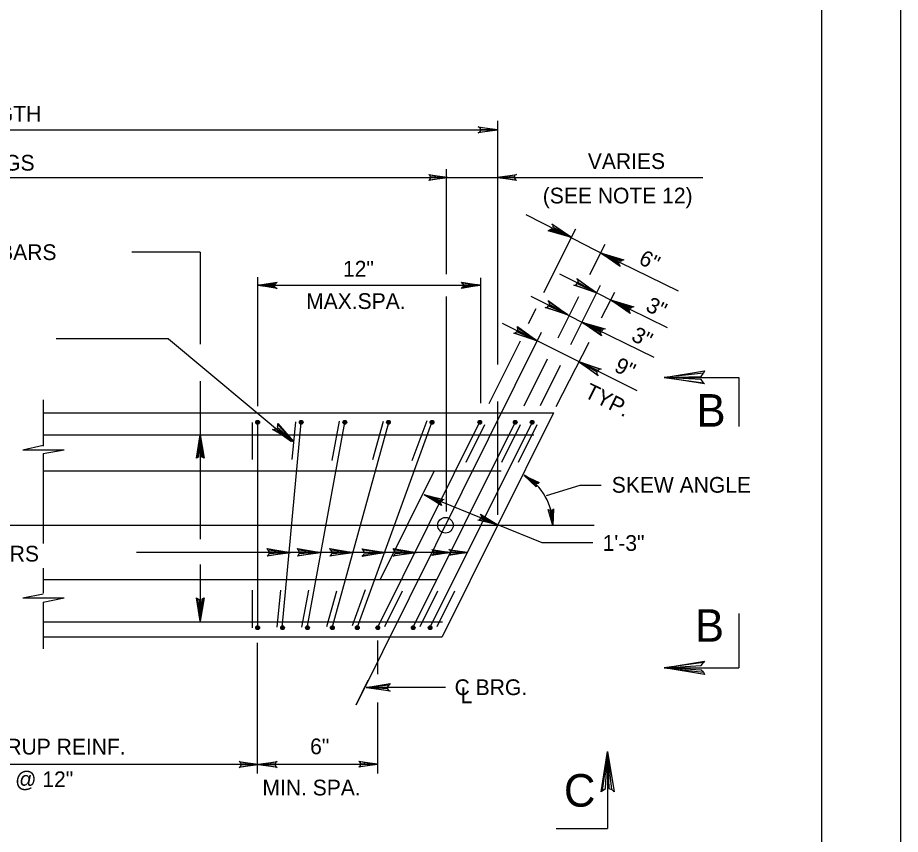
# Model space of a CAD drawing. Extents: x 642009 to 642864, y 298232 to 300014.
# Drawn here: x 642681.6 to 642849.7, y 299702.6 to 299858.2 of the extents above; entities that cross this region are included whole.
import ezdxf

# ---------------------------------------------------------------- set-up
doc = ezdxf.new("R2010")
doc.units = 0
doc.layers.add('2', color=7, linetype='Continuous')
doc.layers.add('PLT-BNDY', color=7, linetype='Continuous')

msp = doc.modelspace()

# ---------------------------------------------------------------- linework, layer by layer
at = {"layer": '2'}
for p, q in [((642834.66, 299998.82), (642834.66, 299434.82)), ((642772.99, 299792.13), (642772.99, 299838.52)), ((642571.23, 299836.82), (642772.99, 299836.82)), ((642763.15, 299829.34), (642763.15, 299809.33)), ((642579.29, 299827.76), (642763.44, 299827.76)), ((642763.44, 299827.76), (642770.63, 299827.76)), ((642770.63, 299827.76), (642812.02, 299827.76)), ((642787.48, 299816.03), (642778.43, 299820.62)), ((642787.77, 299817.89), (642781.72, 299805.75)), ((642793.52, 299812.86), (642787.48, 299816.03)), ((642793.35, 299814.98), (642790.46, 299809.21)), ((642716.34, 299813.53), (642703.33, 299813.53)), ((642716.34, 299813.53), (642716.34, 299795.98)), ((642807.4, 299806.08), (642793.52, 299812.86)), ((642727.21, 299808.79), (642727.21, 299784.21)), ((642769.69, 299808.64), (642769.69, 299784.78)), ((642790.3, 299806.58), (642784.84, 299809.31)), ((642727.21, 299807.21), (642769.69, 299807.21)), ((642792.5, 299807.18), (642786.83, 299795.84)), ((642790.3, 299806.58), (642794.47, 299804.43)), ((642795.19, 299805.86), (642792.7, 299800.97)), ((642763.15, 299805.05), (642763.15, 299764.09)), ((642784.84, 299802.36), (642779.38, 299805.09)), ((642788.37, 299805.04), (642784.41, 299797.12)), ((642805.32, 299799.1), (642794.47, 299804.43)), ((642780.22, 299802.74), (642778.79, 299799.86)), ((642784.84, 299802.36), (642789.01, 299800.2)), ((642802.76, 299793.45), (642789.01, 299800.2)), ((642780.59, 299796.57), (642773.89, 299799.92)), ((642710.28, 299797), (642688.89, 299797)), ((642710.28, 299797), (642733.68, 299777.45)), ((642781.28, 299798.24), (642746.04, 299727.28)), ((642777.26, 299796.59), (642771.28, 299784.6)), ((642788.36, 299792.69), (642780.59, 299796.57)), ((642790.33, 299796.32), (642784.07, 299784.04)), ((642782.42, 299793.14), (642777.96, 299784.21)), ((642784.87, 299791.92), (642781.04, 299784.26)), ((642799.54, 299787.1), (642788.36, 299792.69)), ((642716.34, 299788.93), (642716.34, 299758.86)), ((642804.69, 299789.65), (642818.93, 299789.65)), ((642818.93, 299789.65), (642818.93, 299780.31)), ((642686.39, 299785.36), (642686.39, 299776.59)), ((642772.99, 299763.5), (642772.99, 299785.07)), ((642686.39, 299782.91), (642783.63, 299782.91)), ((642783.63, 299782.91), (642762.43, 299740.22)), ((642726.21, 299781.04), (642726.21, 299774)), ((642727.21, 299781.04), (642727.21, 299741.94)), ((642727.21, 299781.04), (642727.21, 299781.04)), ((642727.21, 299781.04), (642727.21, 299781.04)), ((642727.21, 299781.04), (642727.21, 299781.04)), ((642727.21, 299781.04), (642727.21, 299781.04)), ((642727.21, 299781.04), (642727.21, 299781.04)), ((642727.21, 299781.04), (642727.21, 299781.04)), ((642727.21, 299781.04), (642727.21, 299781.04)), ((642727.21, 299781.04), (642727.21, 299781.04)), ((642731.96, 299741.94), (642735.55, 299781.04)), ((642733.83, 299774), (642734.54, 299781.19)), ((642735.55, 299781.04), (642735.55, 299781.04)), ((642735.55, 299781.04), (642735.55, 299781.04)), ((642735.55, 299781.04), (642735.55, 299781.04)), ((642735.55, 299781.04), (642735.55, 299781.04)), ((642735.55, 299781.04), (642735.55, 299781.04)), ((642735.55, 299781.04), (642735.55, 299781.04)), ((642735.55, 299781.04), (642735.55, 299781.04)), ((642735.55, 299781.04), (642735.55, 299781.04)), ((642735.55, 299781.04), (642735.55, 299781.04)), ((642736.7, 299741.94), (642743.89, 299781.04)), ((642741.44, 299773.86), (642742.88, 299781.33)), ((642741.44, 299741.94), (642752.23, 299781.04)), ((642743.89, 299781.04), (642743.89, 299781.04)), ((642743.89, 299781.04), (642743.89, 299781.04)), ((642743.89, 299781.04), (642743.89, 299781.04)), ((642743.89, 299781.04), (642743.89, 299781.04)), ((642743.89, 299781.04), (642743.89, 299781.04)), ((642743.89, 299781.04), (642743.89, 299781.04)), ((642743.89, 299781.04), (642743.89, 299781.04)), ((642743.89, 299781.04), (642743.89, 299781.04)), ((642743.89, 299781.04), (642743.89, 299781.04)), ((642743.89, 299781.04), (642743.89, 299781.04)), ((642746.19, 299741.94), (642760.42, 299781.04)), ((642749.21, 299774), (642751.22, 299781.33)), ((642750.08, 299741.95), (642769.54, 299781.05)), ((642752.23, 299781.04), (642752.23, 299781.04)), ((642752.23, 299781.04), (642752.23, 299781.04)), ((642752.23, 299781.04), (642752.23, 299781.04)), ((642752.23, 299781.04), (642752.23, 299781.04)), ((642752.23, 299781.04), (642752.23, 299781.04)), ((642752.23, 299781.04), (642752.23, 299781.04)), ((642752.23, 299781.04), (642752.23, 299781.04)), ((642752.23, 299781.04), (642752.23, 299781.04)), ((642752.23, 299781.04), (642752.23, 299781.04)), ((642752.23, 299781.04), (642752.23, 299781.04)), ((642752.23, 299781.04), (642752.23, 299781.04)), ((642756.68, 299773.86), (642759.56, 299781.48)), ((642756.84, 299741.95), (642776.31, 299781.05)), ((642760.05, 299741.95), (642779.52, 299781.05)), ((642760.42, 299781.04), (642760.42, 299781.04)), ((642760.42, 299781.04), (642760.42, 299781.04)), ((642760.42, 299781.04), (642760.42, 299781.04)), ((642760.42, 299781.04), (642760.42, 299781.04)), ((642760.42, 299781.04), (642760.42, 299781.04)), ((642760.42, 299781.04), (642760.42, 299781.04)), ((642760.42, 299781.04), (642760.42, 299781.04)), ((642760.42, 299781.04), (642760.42, 299781.04)), ((642760.42, 299781.04), (642760.42, 299781.04)), ((642760.42, 299781.04), (642760.42, 299781.04)), ((642760.42, 299781.04), (642760.42, 299781.04)), ((642760.42, 299781.04), (642760.42, 299781.04)), ((642766.99, 299773.49), (642770.53, 299780.71)), ((642769.54, 299781.05), (642769.54, 299781.05)), ((642769.54, 299781.05), (642769.54, 299781.05)), ((642769.54, 299781.05), (642769.54, 299781.05)), ((642769.54, 299781.05), (642769.54, 299781.05)), ((642769.54, 299781.05), (642769.54, 299781.05)), ((642769.54, 299781.05), (642769.54, 299781.05)), ((642769.54, 299781.05), (642769.54, 299781.05)), ((642769.54, 299781.05), (642769.54, 299781.05)), ((642769.54, 299781.05), (642769.54, 299781.05)), ((642769.54, 299781.05), (642769.54, 299781.05)), ((642769.54, 299781.05), (642769.54, 299781.05)), ((642769.54, 299781.05), (642769.54, 299781.05)), ((642769.54, 299781.05), (642769.54, 299781.05)), ((642773.75, 299773.49), (642777.3, 299780.71)), ((642776.31, 299781.05), (642776.31, 299781.05)), ((642776.31, 299781.05), (642776.31, 299781.05)), ((642776.31, 299781.05), (642776.31, 299781.05)), ((642776.31, 299781.05), (642776.31, 299781.05)), ((642776.31, 299781.05), (642776.31, 299781.05)), ((642776.31, 299781.05), (642776.31, 299781.05)), ((642776.31, 299781.05), (642776.31, 299781.05)), ((642776.31, 299781.05), (642776.31, 299781.05)), ((642776.31, 299781.05), (642776.31, 299781.05)), ((642776.31, 299781.05), (642776.31, 299781.05)), ((642776.31, 299781.05), (642776.31, 299781.05)), ((642776.31, 299781.05), (642776.31, 299781.05)), ((642776.31, 299781.05), (642776.31, 299781.05)), ((642776.96, 299773.49), (642780.51, 299780.71)), ((642779.52, 299781.05), (642779.52, 299781.05)), ((642779.52, 299781.05), (642779.52, 299781.05)), ((642779.52, 299781.05), (642779.52, 299781.05)), ((642779.52, 299781.05), (642779.52, 299781.05)), ((642779.52, 299781.05), (642779.52, 299781.05)), ((642779.52, 299781.05), (642779.52, 299781.05)), ((642779.52, 299781.05), (642779.52, 299781.05)), ((642779.52, 299781.05), (642779.52, 299781.05)), ((642779.52, 299781.05), (642779.52, 299781.05)), ((642779.52, 299781.05), (642779.52, 299781.05)), ((642779.52, 299781.05), (642779.52, 299781.05)), ((642779.52, 299781.05), (642779.52, 299781.05)), ((642779.52, 299781.05), (642779.52, 299781.05)), ((642686.39, 299778.74), (642779.87, 299778.74)), ((642682.51, 299775.87), (642686.39, 299776.73)), ((642682.51, 299775.87), (642690.41, 299775.87)), ((642686.39, 299775.15), (642690.41, 299775.87)), ((642686.39, 299775.15), (642686.39, 299758.33)), ((642686.39, 299775.15), (642686.39, 299758.04)), ((642686.39, 299771.84), (642773.64, 299771.84)), ((642760.85, 299771.84), (642750.57, 299751.14)), ((642788.65, 299769.08), (642782.18, 299767.07)), ((642792.67, 299769.08), (642788.65, 299769.08)), ((642773.02, 299761.55), (642758.96, 299767.31)), ((642781.42, 299758.12), (642773.02, 299761.55)), ((642671.29, 299761.49), (642791.33, 299761.49)), ((642763.15, 299761.49), (642763.15, 299761.49)), ((642767.6, 299761.49), (642767.6, 299761.49)), ((642791.09, 299758.12), (642781.42, 299758.12)), ((642767.21, 299756.32), (642704.16, 299756.32)), ((642686.39, 299753.3), (642686.39, 299748.56)), ((642716.34, 299753.99), (642716.34, 299743.24)), ((642686.39, 299753.01), (642686.39, 299748.56)), ((642686.39, 299751.14), (642761.42, 299751.14)), ((642682.51, 299747.69), (642686.39, 299748.41)), ((642726.21, 299749.13), (642726.21, 299741.94)), ((642730.95, 299742.09), (642731.67, 299749.13)), ((642735.69, 299742.09), (642736.99, 299749.13)), ((642740.44, 299742.23), (642742.31, 299748.99)), ((642745.33, 299742.38), (642747.77, 299749.28)), ((642751.46, 299742.2), (642754.84, 299749)), ((642758.22, 299742.2), (642761.6, 299749)), ((642761.43, 299742.2), (642764.81, 299749)), ((642682.51, 299747.69), (642690.41, 299747.69)), ((642686.39, 299746.83), (642690.41, 299747.69)), ((642686.39, 299746.83), (642686.39, 299737.92)), ((642686.39, 299743.09), (642762.46, 299743.09)), ((642818.93, 299744.68), (642818.93, 299734.33)), ((642727.21, 299741.94), (642727.21, 299741.94)), ((642727.21, 299741.94), (642727.21, 299741.94)), ((642727.21, 299741.94), (642727.21, 299741.94)), ((642727.21, 299741.94), (642727.21, 299741.94)), ((642727.21, 299741.94), (642727.21, 299741.94)), ((642727.21, 299741.94), (642727.21, 299741.94)), ((642727.21, 299741.94), (642727.21, 299741.94)), ((642731.96, 299741.94), (642731.96, 299741.94)), ((642731.96, 299741.94), (642731.96, 299741.94)), ((642731.96, 299741.94), (642731.96, 299741.94)), ((642731.96, 299741.94), (642731.96, 299741.94)), ((642731.96, 299741.94), (642731.96, 299741.94)), ((642731.96, 299741.94), (642731.96, 299741.94)), ((642736.7, 299741.94), (642736.7, 299741.94)), ((642736.7, 299741.94), (642736.7, 299741.94)), ((642736.7, 299741.94), (642736.7, 299741.94)), ((642736.7, 299741.94), (642736.7, 299741.94)), ((642736.7, 299741.94), (642736.7, 299741.94)), ((642741.44, 299741.94), (642741.44, 299741.94)), ((642741.44, 299741.94), (642741.44, 299741.94)), ((642741.44, 299741.94), (642741.44, 299741.94)), ((642741.44, 299741.94), (642741.44, 299741.94)), ((642746.19, 299741.94), (642746.19, 299741.94)), ((642746.19, 299741.94), (642746.19, 299741.94)), ((642746.19, 299741.94), (642746.19, 299741.94)), ((642750.08, 299741.95), (642750.08, 299741.95)), ((642750.08, 299741.95), (642750.08, 299741.95)), ((642756.84, 299741.95), (642756.84, 299741.95)), ((642756.84, 299741.95), (642756.84, 299741.95)), ((642760.05, 299741.95), (642760.05, 299741.95)), ((642760.05, 299741.95), (642760.05, 299741.95)), ((642686.39, 299740.22), (642762.43, 299740.22)), ((642727.21, 299714.2), (642727.21, 299739.07)), ((642750.13, 299733.15), (642750.13, 299739.52)), ((642804.69, 299734.33), (642818.93, 299734.33)), ((642746.04, 299727.28), (642748.33, 299731.95)), ((642763.01, 299730.59), (642747.91, 299730.59)), ((642750.13, 299714.18), (642750.13, 299727.71)), ((642793.91, 299718.37), (642793.91, 299703.71)), ((642727.36, 299715.93), (642658.07, 299715.93)), ((642750.13, 299715.93), (642727.36, 299715.93)), ((642784.14, 299703.71), (642793.91, 299703.71))]:
    msp.add_line(p, q, dxfattribs=at)
for points in [[(642769.54, 299837.25), (642769.69, 299836.96), (642772.99, 299836.82), (642769.54, 299837.25), (642769.26, 299837.39), (642772.99, 299836.82), (642769.69, 299836.68), (642769.54, 299836.39), (642772.99, 299836.82), (642769.26, 299836.24), (642769.54, 299836.39)], [(642759.99, 299828.19), (642760.13, 299827.91), (642763.44, 299827.76), (642759.99, 299828.19), (642759.84, 299828.34), (642763.44, 299827.76), (642760.13, 299827.62), (642759.99, 299827.33), (642763.44, 299827.76), (642759.84, 299827.19), (642759.99, 299827.33)], [(642776.42, 299827.33), (642776.27, 299827.62), (642772.97, 299827.76), (642776.42, 299827.33), (642776.56, 299827.19), (642772.97, 299827.76), (642776.27, 299827.91), (642776.27, 299828.19), (642772.97, 299827.76), (642776.56, 299828.34), (642776.27, 299828.19)], [(642783.46, 299818.76), (642783.46, 299818.33), (642787.05, 299816.31), (642783.46, 299818.76), (642783.31, 299818.9), (642787.05, 299816.31), (642783.17, 299817.89), (642782.88, 299817.75), (642787.05, 299816.31), (642782.59, 299817.61), (642782.88, 299817.75)], [(642796.13, 299811.08), (642796.13, 299811.36), (642792.54, 299813.38), (642796.13, 299811.08), (642796.28, 299810.79), (642792.54, 299813.38), (642796.42, 299811.79), (642796.71, 299811.94), (642792.54, 299813.38), (642797, 299812.08), (642796.71, 299811.94)], [(642730.66, 299806.78), (642730.52, 299806.92), (642727.21, 299807.21), (642730.66, 299806.78), (642730.95, 299806.63), (642727.21, 299807.21), (642730.52, 299807.35), (642730.66, 299807.49), (642727.21, 299807.21), (642730.95, 299807.78), (642730.66, 299807.49)], [(642766.23, 299807.64), (642766.38, 299807.35), (642769.68, 299807.21), (642766.23, 299807.64), (642766.09, 299807.78), (642769.68, 299807.21), (642766.38, 299806.92), (642766.23, 299806.78), (642769.68, 299807.21), (642766.09, 299806.63), (642766.23, 299806.78)], [(642788.22, 299808.25), (642788.22, 299807.81), (642791.81, 299805.8), (642788.22, 299808.25), (642788.07, 299808.53), (642791.81, 299805.8), (642788.07, 299807.53), (642787.78, 299807.24), (642791.81, 299805.8), (642787.5, 299807.24), (642787.78, 299807.24)], [(642782.75, 299804.02), (642782.75, 299803.59), (642786.35, 299801.58), (642782.75, 299804.02), (642782.61, 299804.31), (642786.35, 299801.58), (642782.61, 299803.3), (642782.32, 299803.01), (642786.35, 299801.58), (642782.04, 299803.01), (642782.32, 299803.01)], [(642798.06, 299802.13), (642798.06, 299802.41), (642794.47, 299804.43), (642798.06, 299802.13), (642798.21, 299801.84), (642794.47, 299804.43), (642798.35, 299802.84), (642798.49, 299802.99), (642794.47, 299804.43), (642798.93, 299803.13), (642798.49, 299802.99)], [(642792.6, 299797.9), (642792.6, 299798.19), (642789.01, 299800.2), (642792.6, 299797.9), (642792.75, 299797.61), (642789.01, 299800.2), (642792.89, 299798.62), (642793.03, 299798.76), (642789.01, 299800.2), (642793.46, 299798.91), (642793.03, 299798.76)], [(642776.74, 299799.07), (642776.74, 299798.64), (642780.48, 299796.63), (642776.74, 299799.07), (642776.74, 299799.36), (642780.48, 299796.63), (642776.6, 299798.35), (642776.31, 299798.07), (642780.48, 299796.63), (642776.02, 299798.07), (642776.31, 299798.07)], [(642791.95, 299790.24), (642791.95, 299790.68), (642788.36, 299792.69), (642791.95, 299790.24), (642792.09, 299789.96), (642788.36, 299792.69), (642792.09, 299790.96), (642792.38, 299791.25), (642788.36, 299792.69), (642792.67, 299791.25), (642792.38, 299791.25)], [(642812.15, 299788.62), (642811.73, 299789.24), (642804.69, 299789.65), (642812.15, 299788.62), (642812.35, 299788.41), (642804.69, 299789.65), (642811.73, 299789.86), (642812.15, 299790.48), (642804.69, 299789.65), (642812.35, 299790.9), (642812.15, 299790.48)], [(642731.09, 299780.61), (642730.95, 299780.18), (642734.11, 299777.45), (642731.09, 299780.61), (642731.09, 299780.9), (642734.11, 299777.45), (642730.81, 299779.89), (642730.38, 299779.75), (642734.11, 299777.45), (642730.09, 299779.75), (642730.38, 299779.75)], [(642715.76, 299774.43), (642716.05, 299774.58), (642716.34, 299778.74), (642715.76, 299774.43), (642715.62, 299774.29), (642716.34, 299778.74), (642716.48, 299774.58), (642716.91, 299774.43), (642716.34, 299778.74), (642717.06, 299774.29), (642716.91, 299774.43)], [(642715.76, 299774.43), (642716.05, 299774.58), (642716.34, 299778.74), (642715.76, 299774.43), (642715.62, 299774.29), (642716.34, 299778.74), (642716.48, 299774.58), (642716.91, 299774.43), (642716.34, 299778.74), (642717.06, 299774.29), (642716.91, 299774.43)], [(642732.24, 299779.03), (642732.24, 299778.89), (642733.68, 299777.45), (642732.24, 299779.03), (642732.24, 299779.18), (642733.68, 299777.45), (642732.1, 299778.74), (642731.96, 299778.74), (642733.68, 299777.45), (642731.81, 299778.74), (642731.96, 299778.74)], [(642780.31, 299768.94), (642780.31, 299769.23), (642778.01, 299770.95), (642780.31, 299768.94), (642780.31, 299768.8), (642778.01, 299770.95), (642780.45, 299769.52), (642780.74, 299769.52), (642778.01, 299770.95), (642780.88, 299769.66), (642780.74, 299769.52)], [(642762.19, 299765.49), (642762.16, 299765.79), (642758.96, 299767.31), (642762.19, 299765.49), (642762.3, 299765.27), (642758.96, 299767.31), (642762.3, 299766.13), (642762.52, 299766.33), (642758.96, 299767.31), (642762.77, 299766.42), (642762.52, 299766.33)], [(642769.8, 299763.37), (642769.82, 299763.08), (642773.02, 299761.55), (642769.8, 299763.37), (642769.68, 299763.6), (642773.02, 299761.55), (642769.68, 299762.73), (642769.46, 299762.54), (642773.02, 299761.55), (642769.21, 299762.45), (642769.46, 299762.54)], [(642783.61, 299764.48), (642783.33, 299764.34), (642783.47, 299761.47), (642783.61, 299764.48), (642783.61, 299764.63), (642783.47, 299761.47), (642783.04, 299764.34), (642782.9, 299764.34), (642783.47, 299761.47), (642782.61, 299764.48), (642782.9, 299764.34)], [(642729.23, 299756.75), (642729.37, 299756.46), (642733.54, 299756.32), (642729.23, 299756.75), (642729.08, 299757.04), (642733.54, 299756.32), (642729.37, 299756.03), (642729.23, 299755.74), (642733.54, 299756.32), (642729.08, 299755.6), (642729.23, 299755.74)], [(642734.98, 299756.75), (642735.12, 299756.46), (642739.29, 299756.32), (642734.98, 299756.75), (642734.83, 299757.04), (642739.29, 299756.32), (642735.12, 299756.03), (642734.98, 299755.74), (642739.29, 299756.32), (642734.83, 299755.6), (642734.98, 299755.74)], [(642741.16, 299756.75), (642741.3, 299756.46), (642745.47, 299756.32), (642741.16, 299756.75), (642741.01, 299757.04), (642745.47, 299756.32), (642741.3, 299756.03), (642741.16, 299755.74), (642745.47, 299756.32), (642741.01, 299755.6), (642741.16, 299755.74)], [(642747.31, 299756.72), (642747.46, 299756.44), (642751.63, 299756.29), (642747.31, 299756.72), (642747.17, 299757.01), (642751.63, 299756.29), (642747.46, 299756.01), (642747.31, 299755.72), (642751.63, 299756.29), (642747.17, 299755.57), (642747.31, 299755.72)], [(642753.23, 299756.75), (642753.38, 299756.46), (642757.54, 299756.32), (642753.23, 299756.75), (642753.09, 299757.04), (642757.54, 299756.32), (642753.38, 299756.03), (642753.23, 299755.74), (642757.54, 299756.32), (642753.09, 299755.6), (642753.23, 299755.74)], [(642760.63, 299756.71), (642760.76, 299756.47), (642763.98, 299756.29), (642760.63, 299756.71), (642760.46, 299756.86), (642763.98, 299756.29), (642760.76, 299756.13), (642760.64, 299755.89), (642763.98, 299756.29), (642760.46, 299755.73), (642760.64, 299755.89)], [(642763.87, 299756.74), (642764, 299756.5), (642767.21, 299756.32), (642763.87, 299756.74), (642763.7, 299756.89), (642767.21, 299756.32), (642764, 299756.16), (642763.88, 299755.92), (642767.21, 299756.32), (642763.7, 299755.76), (642763.88, 299755.92)], [(642716.91, 299747.55), (642716.62, 299747.41), (642716.34, 299743.24), (642716.91, 299747.55), (642717.06, 299747.69), (642716.34, 299743.24), (642716.19, 299747.26), (642715.76, 299747.55), (642716.34, 299743.24), (642715.62, 299747.69), (642715.76, 299747.55)], [(642716.91, 299747.55), (642716.62, 299747.41), (642716.34, 299743.24), (642716.91, 299747.55), (642717.06, 299747.69), (642716.34, 299743.24), (642716.19, 299747.26), (642715.76, 299747.55), (642716.34, 299743.24), (642715.62, 299747.69), (642715.76, 299747.55)], [(642812.15, 299733.5), (642811.73, 299733.91), (642804.69, 299734.33), (642812.15, 299733.5), (642812.35, 299733.08), (642804.69, 299734.33), (642811.73, 299734.74), (642812.15, 299735.36), (642804.69, 299734.33), (642812.35, 299735.57), (642812.15, 299735.36)], [(642752.23, 299730.01), (642752.08, 299730.3), (642747.91, 299730.59), (642752.23, 299730.01), (642752.51, 299729.87), (642747.91, 299730.59), (642752.08, 299730.73), (642752.23, 299731.02), (642747.91, 299730.59), (642752.51, 299731.31), (642752.23, 299731.02)], [(642792.88, 299710.92), (642793.5, 299711.33), (642793.91, 299718.37), (642792.88, 299710.92), (642792.67, 299710.71), (642793.91, 299718.37), (642794.12, 299711.33), (642794.74, 299711.12), (642793.91, 299718.37), (642795.15, 299710.71), (642794.74, 299711.12)], [(642723.91, 299716.36), (642724.05, 299716.07), (642727.36, 299715.93), (642723.91, 299716.36), (642723.76, 299716.5), (642727.36, 299715.93), (642724.05, 299715.78), (642723.91, 299715.49), (642727.36, 299715.93), (642723.76, 299715.35), (642723.91, 299715.49)], [(642730.81, 299715.49), (642730.66, 299715.78), (642727.36, 299715.93), (642730.81, 299715.49), (642730.95, 299715.35), (642727.36, 299715.93), (642730.66, 299716.07), (642730.81, 299716.36), (642727.36, 299715.93), (642730.95, 299716.5), (642730.81, 299716.36)], [(642746.68, 299716.39), (642746.82, 299716.1), (642750.13, 299715.96), (642746.68, 299716.39), (642746.53, 299716.54), (642750.13, 299715.96), (642746.82, 299715.82), (642746.68, 299715.53), (642750.13, 299715.96), (642746.53, 299715.39), (642746.68, 299715.53)], [(642747.48, 299716.36), (642747.63, 299716.07), (642750.13, 299715.96)]]:
    msp.add_lwpolyline(points, dxfattribs=at)
for centre, radius in [((642727.26, 299781.11), 0.356), ((642727.26, 299781.11), 0.197), ((642727.26, 299781.11), 0.0936), ((642735.56, 299781.11), 0.356), ((642735.56, 299781.11), 0.197), ((642735.56, 299781.11), 0.0936), ((642743.87, 299781.11), 0.356), ((642743.87, 299781.11), 0.197), ((642743.87, 299781.11), 0.0936), ((642743.87, 299781.11), 0.0936), ((642752.17, 299781.11), 0.356), ((642752.17, 299781.11), 0.197), ((642752.17, 299781.11), 0.0936), ((642760.47, 299781.11), 0.356), ((642760.47, 299781.11), 0.197), ((642760.47, 299781.11), 0.0936), ((642769.56, 299781.11), 0.356), ((642769.56, 299781.11), 0.197), ((642769.56, 299781.11), 0.0936), ((642776.32, 299781.11), 0.356), ((642776.32, 299781.11), 0.197), ((642776.32, 299781.11), 0.0936), ((642779.53, 299781.11), 0.356), ((642779.53, 299781.11), 0.197), ((642779.53, 299781.11), 0.0936), ((642763.03, 299761.49), 1.48), ((642727.26, 299741.97), 0.356), ((642727.26, 299741.97), 0.197), ((642727.26, 299741.97), 0.0936), ((642732.01, 299741.97), 0.356), ((642732.01, 299741.97), 0.197), ((642732.01, 299741.97), 0.0936), ((642736.75, 299741.97), 0.356), ((642736.75, 299741.97), 0.197), ((642736.75, 299741.97), 0.0936), ((642741.49, 299741.97), 0.356), ((642741.49, 299741.97), 0.197), ((642741.49, 299741.97), 0.0936), ((642746.24, 299741.97), 0.356), ((642746.24, 299741.97), 0.197), ((642746.24, 299741.97), 0.0936), ((642750.13, 299741.97), 0.356), ((642750.13, 299741.97), 0.197), ((642750.13, 299741.97), 0.0936), ((642756.89, 299741.97), 0.356), ((642756.89, 299741.97), 0.197), ((642756.89, 299741.97), 0.0936), ((642760.1, 299741.97), 0.356), ((642760.1, 299741.97), 0.197), ((642760.1, 299741.97), 0.0936)]:
    msp.add_circle(centre, radius, dxfattribs=at)
msp.add_arc((642772.47, 299761.51), 11.02, 359.4624, 59.8257, dxfattribs=at)
at = {"layer": 'PLT-BNDY'}
msp.add_lwpolyline([(642008.66, 300013.82), (642849.66, 300013.82), (642849.66, 299419.82), (642008.66, 299419.82)], close=True, dxfattribs=at)

# ---------------------------------------------------------------- texts
at = {"layer": '2'}
for s, height, p in [('BEAM LENGTH', 2.9998, (642657.3, 299838.38)), ('VARIES', 3, (642790.14, 299829.37)), ('C.C. BEARINGS', 2.9998, (642654.91, 299829.06)), ('(SEE NOTE 12)', 2.9998, (642781.56, 299822.81)), ('#4 LONGITUDINAL REBARS', 2.9998, (642636.12, 299812.02)), ('12"', 3, (642743.51, 299808.87)), ('MAX.SPA.', 3, (642736.49, 299802.7)), ('B', 6.21, (642810.84, 299780.27)), ('SKEW ANGLE', 3, (642794.7, 299767.69)), ('1\'-3"', 3, (642792.95, 299756.61)), ('TOP & BOT. TRANS. BARS', 2.9998, (642635.24, 299754.58)), ('B', 6.21, (642810.54, 299739.29)), ('C BRG.', 3, (642764.77, 299729.13)), ('L', 3, (642765.91, 299727.59)), ('TYP. STIRRUP REINF.', 2.9998, (642660.23, 299717.81)), ('6"', 3, (642737.25, 299717.86)), ('SPA. @ 12"', 3, (642670.81, 299711.59)), ('MIN. SPA. ', 3, (642728.17, 299710.01)), ('C', 6.21, (642785.59, 299707.87))]:
    msp.add_text(s, height=height, dxfattribs=at).set_placement(p)
for s, p in [('6"', (642799.63, 299811.42)), ('3"', (642800.95, 299802.47)), ('3"', (642798.22, 299796.79)), ('9"', (642794.96, 299790.94)), ('TYP.', (642789.26, 299786))]:
    msp.add_text(s, height=3, rotation=333.4537, dxfattribs=at).set_placement(p)

doc.saveas('drawing.dxf')
